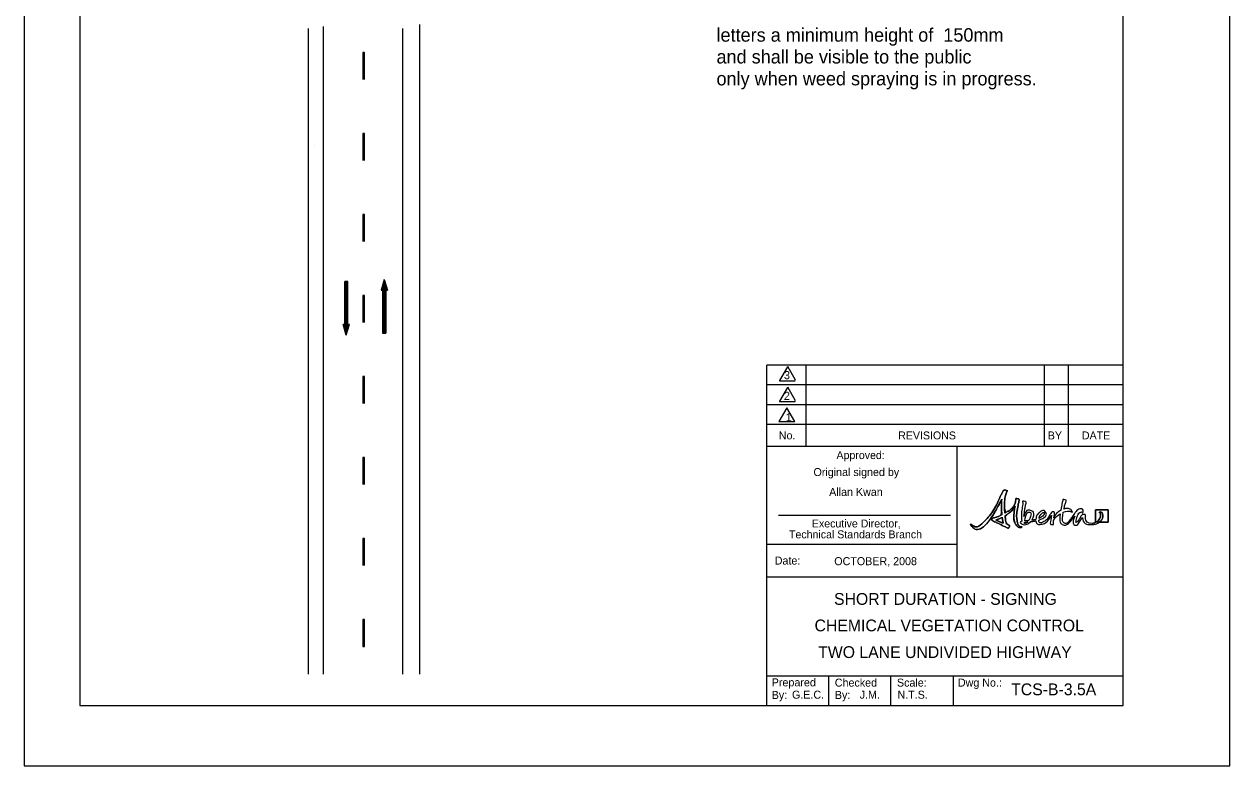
# Model space of a CAD drawing. Extents: x 1578 to 1794, y 169 to 448.
# Drawn here: x 1578.5 to 1794.5, y 169 to 301.9 of the extents above; entities that cross this region are included whole.
import ezdxf

# ---------------------------------------------------------------- set-up
doc = ezdxf.new("R2010")
doc.units = 0
for name, color, linetype in [('Level 10', 7, 'Continuous'), ('Level 2', 7, 'Continuous'), ('Level 53', 7, 'Continuous'), ('Level 60', 7, 'Continuous')]:
    doc.layers.add(name, color=color, linetype=linetype)

msp = doc.modelspace()

# ---------------------------------------------------------------- linework, layer by layer
at = {"layer": 'Level 10'}
for p, q in [((1629.33, 301.16), (1629.33, 185.45)), ((1632.06, 301.53), (1632.06, 185.45)), ((1646.28, 301.16), (1646.28, 185.45)), ((1649.3, 301.9), (1649.3, 185.45)), ((1630.42, 280.2), (1630.42, 280.2)), ((1635.9, 248.11), (1635.9, 255.85)), ((1636.48, 255.85), (1635.9, 255.85)), ((1635.9, 247.15), (1635.9, 255.85)), ((1635.97, 246.9), (1635.97, 255.85)), ((1636.05, 246.66), (1636.05, 255.85)), ((1636.12, 246.42), (1636.12, 255.85)), ((1636.19, 246.18), (1636.19, 255.85)), ((1636.26, 246.42), (1636.26, 255.85)), ((1636.34, 246.66), (1636.34, 255.85)), ((1636.41, 246.9), (1636.41, 255.85)), ((1636.48, 248.11), (1636.48, 255.85)), ((1636.48, 247.15), (1636.48, 255.85)), ((1642.99, 256.21), (1642.41, 254.28)), ((1642.62, 255), (1642.62, 254.28)), ((1642.7, 255.25), (1642.7, 246.54)), ((1642.77, 255.49), (1642.77, 246.54)), ((1642.84, 255.73), (1642.84, 246.54)), ((1642.91, 255.97), (1642.91, 246.54)), ((1642.99, 256.21), (1642.99, 246.54)), ((1642.99, 256.21), (1643.57, 254.28)), ((1643.06, 255.97), (1643.06, 246.54)), ((1643.13, 255.73), (1643.13, 246.54)), ((1643.2, 255.49), (1643.2, 246.54)), ((1643.28, 255.25), (1643.28, 246.54)), ((1643.35, 255), (1643.35, 254.28)), ((1642.41, 254.28), (1642.7, 254.28)), ((1642.48, 254.52), (1642.48, 254.28)), ((1642.55, 254.76), (1642.55, 254.28)), ((1642.7, 254.28), (1642.7, 246.54)), ((1643.28, 254.28), (1643.28, 246.54)), ((1643.28, 254.28), (1643.57, 254.28)), ((1643.42, 254.76), (1643.42, 254.28)), ((1643.49, 254.52), (1643.49, 254.28)), ((1636.19, 246.18), (1635.61, 248.11)), ((1635.9, 248.11), (1635.61, 248.11)), ((1635.68, 247.87), (1635.68, 248.11)), ((1635.75, 247.63), (1635.75, 248.11)), ((1635.83, 247.39), (1635.83, 248.11)), ((1636.19, 246.18), (1636.77, 248.11)), ((1636.77, 248.11), (1636.48, 248.11)), ((1636.55, 247.39), (1636.55, 248.11)), ((1636.63, 247.63), (1636.63, 248.11)), ((1636.7, 247.87), (1636.7, 248.11)), ((1642.7, 246.54), (1643.28, 246.54))]:
    msp.add_line(p, q, dxfattribs=at)
at = {"layer": 'Level 2'}
for p, q in [((1639.15, 296.86), (1639.15, 292.02)), ((1639.44, 296.86), (1639.15, 296.86)), ((1639.44, 292.02), (1639.44, 296.86)), ((1639.15, 282.35), (1639.15, 277.51)), ((1639.44, 282.35), (1639.15, 282.35)), ((1639.44, 277.51), (1639.44, 282.35)), ((1639.15, 267.83), (1639.15, 262.99)), ((1639.44, 267.83), (1639.15, 267.83)), ((1639.44, 262.99), (1639.44, 267.83)), ((1639.15, 253.32), (1639.15, 248.48)), ((1639.44, 253.32), (1639.15, 253.32)), ((1639.44, 248.48), (1639.44, 253.32)), ((1639.15, 238.8), (1639.15, 233.97)), ((1639.44, 238.8), (1639.15, 238.8)), ((1639.44, 233.97), (1639.44, 238.8)), ((1639.15, 224.29), (1639.15, 219.45)), ((1639.44, 224.29), (1639.15, 224.29)), ((1639.44, 219.45), (1639.44, 224.29)), ((1639.15, 209.78), (1639.15, 204.94)), ((1639.44, 209.78), (1639.15, 209.78)), ((1639.44, 204.94), (1639.44, 209.78)), ((1639.15, 195.26), (1639.15, 190.42)), ((1639.44, 195.26), (1639.15, 195.26)), ((1639.44, 190.42), (1639.44, 195.26)), ((1639.15, 190.42), (1639.44, 190.42))]:
    msp.add_line(p, q, dxfattribs=at)
at = {"layer": 'Level 53'}
msp.add_line((1771.03, 212.68), (1770.48, 212.68), dxfattribs=at)
msp.add_lwpolyline([(1771.03, 212.68), (1772.65, 212.68), (1772.65, 214.91), (1770.42, 214.91), (1770.42, 212.68), (1770.48, 212.68)], dxfattribs=at)
for points, degree in [([(1757.05, 211.87), (1756.81, 211.9), (1756.49, 212.23), (1756.4, 212.77), (1756.23, 213.73), (1756.33, 214.69), (1756.61, 216.11), (1756.67, 216.38), (1756.85, 216.84), (1756.27, 216.93), (1756.08, 216.96), (1756.18, 216.87), (1756.12, 216.62), (1755.9, 215.57), (1755.03, 214.8), (1754.16, 214.29), (1754.07, 215.5), (1754.11, 216.85), (1754.34, 217.67), (1754.53, 218.37), (1754.76, 218.24), (1754.48, 218.39), (1754.18, 218.54), (1753.86, 218.34), (1753.6, 217.82), (1753.34, 217.3), (1752.14, 214.49), (1750.23, 212.59), (1749.25, 211.61), (1748.37, 212.11), (1748.19, 212.26), (1748.05, 212.39), (1747.99, 212.2), (1748.17, 212.01), (1748.96, 211.15), (1750.12, 211.64), (1750.54, 212.06), (1751.7, 213.22), (1753.05, 215.73), (1753.6, 216.79), (1753.55, 216.19), (1753.53, 215.19), (1753.64, 214.01), (1753.05, 213.72), (1752.52, 213.55), (1752.27, 213.49), (1752, 213.42), (1751.83, 213.31), (1751.83, 213.18), (1751.82, 213.04), (1752, 212.93), (1752.27, 212.8), (1752.74, 212.58), (1754.11, 211.93), (1754.45, 211.74), (1754.73, 211.57), (1754.88, 211.7), (1754.96, 211.88), (1755.07, 212.12), (1754.77, 212.25), (1754.47, 212.34), (1754.35, 212.74), (1754.26, 213.28), (1754.2, 213.87), (1754.9, 214.3), (1755.59, 214.87), (1755.98, 215.58), (1755.88, 214.98), (1755.63, 212.95), (1756.27, 212.1), (1756.41, 211.91), (1756.72, 211.7), (1757.03, 211.73), (1757.17, 211.74), (1757.24, 211.84), (1757.23, 211.87), (1757.21, 211.9), (1757.13, 211.86), (1757.05, 211.87)], 3), ([(1754.16, 214.29), (1754.07, 215.5), (1754.11, 216.85), (1754.34, 217.67), (1754.53, 218.37), (1754.76, 218.24), (1754.48, 218.39), (1754.18, 218.54), (1753.86, 218.34), (1753.6, 217.82), (1753.34, 217.3), (1752.14, 214.49), (1750.23, 212.59), (1749.25, 211.61), (1748.37, 212.11), (1748.19, 212.26), (1748.05, 212.39), (1747.99, 212.2), (1748.17, 212.01), (1748.96, 211.15), (1750.12, 211.64), (1750.54, 212.06), (1751.7, 213.22), (1753.05, 215.73), (1753.6, 216.79)], 3), ([(1753.6, 216.79), (1753.55, 216.19), (1753.53, 215.19), (1753.64, 214.01)], 2), ([(1757.05, 211.87), (1756.81, 211.9), (1756.49, 212.23), (1756.4, 212.77), (1756.23, 213.73), (1756.33, 214.69), (1756.61, 216.11), (1756.67, 216.38), (1756.85, 216.84), (1756.27, 216.93), (1756.08, 216.96), (1756.18, 216.87), (1756.12, 216.62), (1755.9, 215.57), (1755.03, 214.8), (1754.16, 214.29)], 3), ([(1757.58, 213.71), (1757.63, 214.28), (1757.72, 214.97), (1757.85, 215.61), (1757.9, 215.88), (1758.09, 216.35), (1757.5, 216.44), (1757.32, 216.47), (1757.35, 216.38), (1757.36, 216.13), (1757.38, 215.79), (1757.01, 213.75), (1757.2, 212.86)], 3), ([(1764.74, 215.05), (1764.8, 215.35), (1764.88, 215.65), (1764.96, 215.94), (1765.04, 216.21), (1765.26, 216.68), (1764.68, 216.77), (1764.5, 216.8), (1764.57, 216.71), (1764.51, 216.46), (1764.4, 216), (1764.26, 215.41), (1764.16, 214.81)], 3), ([(1753.64, 214.01), (1753.05, 213.72), (1752.52, 213.55), (1752.27, 213.49), (1752, 213.42), (1751.83, 213.31), (1751.83, 213.18), (1751.82, 213.04), (1752, 212.93), (1752.27, 212.8), (1752.74, 212.58), (1754.11, 211.93), (1754.45, 211.74), (1754.73, 211.57), (1754.88, 211.7), (1754.96, 211.88), (1755.07, 212.12), (1754.77, 212.25), (1754.47, 212.34)], 3), ([(1754.2, 213.87), (1754.9, 214.3), (1755.59, 214.87), (1755.98, 215.58)], 2), ([(1754.47, 212.34), (1754.35, 212.74), (1754.26, 213.28), (1754.2, 213.87)], 2), ([(1755.98, 215.58), (1755.88, 214.98), (1755.63, 212.95), (1756.27, 212.1), (1756.41, 211.91), (1756.72, 211.7), (1757.03, 211.73), (1757.17, 211.74), (1757.24, 211.84), (1757.23, 211.87), (1757.21, 211.9), (1757.13, 211.86), (1757.05, 211.87)], 3), ([(1759.02, 213.05), (1759.44, 213.72), (1759.4, 214.63), (1758.79, 214.78), (1758.09, 214.96), (1757.73, 214.28), (1757.58, 213.71)], 3), ([(1757.73, 212.92), (1757.83, 213.64), (1758.2, 214.63), (1758.66, 214.47), (1758.93, 214.38), (1758.79, 213.54), (1758.45, 212.98)], 3), ([(1760.25, 213.07), (1760.34, 213.1), (1760.43, 213.13), (1760.5, 213.16), (1761.38, 213.55), (1761.69, 214.15), (1761.46, 214.5), (1761.25, 214.85), (1760.64, 214.74), (1760.16, 214.24), (1759.92, 213.99), (1759.74, 213.56), (1759.72, 213.17)], 3), ([(1759.73, 212.95), (1759.78, 212.55), (1760.03, 212.25), (1760.63, 212.31), (1761.47, 212.39), (1762.23, 213.43), (1762.51, 213.93)], 3), ([(1762.92, 213.49), (1762.98, 213.76), (1763.06, 214.07), (1763.07, 214.27), (1763.08, 214.49), (1762.93, 214.54), (1762.87, 214.56), (1762.74, 214.59), (1762.59, 214.53), (1762.44, 214.32), (1762.09, 213.82), (1761.64, 213.03), (1760.96, 212.7), (1760.47, 212.47), (1760.26, 212.7), (1760.25, 213.07)], 3), ([(1760.72, 214.19), (1761.02, 214.47), (1761.16, 214.45), (1761.2, 214.37), (1761.28, 214.21), (1760.94, 213.65), (1760.27, 213.34)], 3), ([(1760.27, 213.34), (1760.33, 213.64), (1760.49, 213.97), (1760.72, 214.19)], 2), ([(1762.51, 213.93), (1762.46, 213.39), (1762.11, 212.22), (1762.7, 212.28), (1762.94, 212.3), (1762.84, 212.34), (1762.85, 212.54), (1762.9, 213.25), (1763.49, 213.85), (1764.07, 214.21)], 3), ([(1764.16, 214.81), (1763.69, 214.54), (1763.24, 214.09), (1762.92, 213.49)], 2), ([(1764.07, 214.21), (1763.97, 213.35), (1764.01, 212.57), (1764.4, 212.33), (1765.12, 211.88), (1766.14, 213.07), (1766.71, 213.79)], 3), ([(1769.79, 212.48), (1768.88, 212.48), (1768.64, 213.19), (1768.6, 213.54), (1768.57, 213.78), (1768.62, 214.12), (1768.21, 214.07), (1767.93, 214.04), (1767.67, 213.49), (1767.32, 213.02), (1767.01, 212.63), (1766.87, 212.66), (1766.94, 213.01), (1767.03, 213.43), (1767.39, 214.44), (1767.8, 214.51), (1767.99, 214.55), (1768.05, 214.21), (1768.14, 214.42), (1768.23, 214.63), (1768.15, 215.08), (1767.72, 215.08), (1767.43, 215.08), (1767.07, 214.77), (1766.78, 214.41), (1766.53, 214.1), (1765.24, 212.2), (1764.7, 212.61), (1764.45, 212.8), (1764.47, 213.58), (1764.63, 214.5)], 3), ([(1764.63, 214.5), (1765.27, 214.74), (1765.8, 214.66), (1766.1, 214.52), (1766.25, 214.45), (1766.27, 214.46), (1766.21, 214.62), (1766.11, 214.86), (1765.6, 215.24), (1764.79, 215.06), (1764.78, 215.06), (1764.76, 215.06), (1764.74, 215.05)], 3), ([(1770.42, 214.91), (1770.42, 214.91), (1770.42, 212.68), (1770.42, 212.68), (1770.42, 212.68), (1770.48, 212.68), (1770.48, 212.68), (1770.97, 212.97), (1771.29, 213.52), (1771.29, 213.98), (1771.29, 214.37), (1771.08, 214.35), (1771.1, 214.41), (1771.17, 214.56), (1771.67, 214.47), (1771.69, 213.92), (1771.72, 213.45), (1771.47, 212.99), (1771.03, 212.68), (1771.03, 212.68), (1772.65, 212.68), (1772.65, 212.68), (1772.65, 212.68), (1772.65, 214.91), (1772.65, 214.91), (1772.65, 214.91), (1770.42, 214.91), (1770.42, 214.91)], 3), ([(1770.48, 212.68), (1770.97, 212.97), (1771.29, 213.52), (1771.29, 213.98), (1771.29, 214.37), (1771.08, 214.35), (1771.1, 214.41), (1771.17, 214.56), (1771.67, 214.47), (1771.69, 213.92), (1771.72, 213.45), (1771.47, 212.99), (1771.03, 212.68)], 3), ([(1752.57, 213.08), (1752.88, 213.19), (1753.28, 213.36), (1753.69, 213.58)], 2), ([(1752.57, 213.08), (1752.88, 213.19), (1753.28, 213.36), (1753.69, 213.58), (1753.75, 213.1), (1753.81, 212.76), (1753.87, 212.51), (1753.57, 212.62), (1753.14, 212.79), (1752.57, 213.08)], 3), ([(1753.87, 212.51), (1753.57, 212.62), (1753.14, 212.79), (1752.57, 213.08)], 2), ([(1753.69, 213.58), (1753.75, 213.1), (1753.81, 212.76), (1753.87, 212.51)], 2), ([(1757.2, 212.86), (1756.95, 212.78), (1756.85, 212.59), (1757.17, 212.39), (1757.4, 212.25), (1757.89, 212.21), (1758.38, 212.45), (1758.56, 212.54), (1758.71, 212.66), (1758.84, 212.8)], 3), ([(1757.66, 212.49), (1757.69, 212.51), (1757.71, 212.55), (1757.71, 212.6), (1757.71, 212.63), (1757.71, 212.67), (1757.71, 212.7)], 3), ([(1757.86, 212.49), (1757.78, 212.48), (1757.71, 212.48), (1757.66, 212.49)], 2), ([(1757.71, 212.7), (1757.84, 212.7), (1758.04, 212.72), (1758.27, 212.74)], 2), ([(1758.45, 212.98), (1758.22, 212.96), (1757.98, 212.94), (1757.73, 212.92)], 2), ([(1758.27, 212.74), (1758.15, 212.61), (1758.01, 212.51), (1757.86, 212.49)], 2), ([(1758.84, 212.8), (1759.14, 212.84), (1759.45, 212.89), (1759.73, 212.95)], 2), ([(1759.72, 213.17), (1759.52, 213.12), (1759.28, 213.08), (1759.02, 213.05)], 2), ([(1766.71, 213.79), (1766.42, 213.15), (1766.26, 212.32), (1766.69, 212.19), (1767.19, 212.05), (1767.59, 212.88), (1768.06, 213.53)], 3), ([(1768.06, 213.53), (1768.11, 213.07), (1768.42, 212.27), (1769.65, 212.27), (1770.21, 212.27), (1770.68, 212.43), (1771.03, 212.68)], 3), ([(1770.48, 212.68), (1770.28, 212.56), (1770.04, 212.48), (1769.79, 212.48)], 2)]:
    msp.add_open_spline(points, degree=degree, dxfattribs=at)
at = {"layer": 'Level 60'}
for p, q in [((1711.5, 234.37), (1711.5, 240.84)), ((1775.38, 240.84), (1711.5, 240.84)), ((1718.59, 234.37), (1718.59, 240.84)), ((1761.18, 240.84), (1761.18, 226.29)), ((1765.49, 240.84), (1765.49, 226.29)), ((1775.38, 237.29), (1711.5, 237.29)), ((1711.5, 226.29), (1711.5, 234.37)), ((1775.38, 233.75), (1711.5, 233.75)), ((1718.59, 226.29), (1718.59, 234.37)), ((1775.38, 230.2), (1711.5, 230.2)), ((1745.72, 228.68), (1745.72, 228.68)), ((1711.5, 179.83), (1711.5, 226.29)), ((1711.5, 226.29), (1775.38, 226.29)), ((1745.55, 226.29), (1745.55, 202.88)), ((1745.57, 226.29), (1745.57, 226.29)), ((1713.61, 213.98), (1744.41, 213.98)), ((1711.5, 208.74), (1745.55, 208.74)), ((1711.5, 202.88), (1775.35, 202.88)), ((1711.5, 185.15), (1775.35, 185.15)), ((1722.63, 179.83), (1722.63, 185.15)), ((1733.76, 179.83), (1733.76, 185.15)), ((1744.89, 185.15), (1744.89, 179.83)), ((1588.47, 179.83), (1588.47, 179.83)), ((1726.97, 179.83), (1726.97, 179.83)), ((1775.35, 179.83), (1775.35, 179.83)), ((1775.35, 179.83), (1775.35, 179.83)), ((1578.47, 169.02), (1578.47, 169.02))]:
    msp.add_line(p, q, dxfattribs=at)
for points in [[(1794.47, 448.02), (1578.47, 448.02), (1578.47, 169.02), (1794.47, 169.02)], [(1775.35, 437.21), (1588.47, 437.21), (1588.47, 179.83), (1775.35, 179.83)], [(1715.12, 233.18), (1713.7, 230.71), (1716.54, 230.71)]]:
    msp.add_lwpolyline(points, close=True, dxfattribs=at)
for points in [[(1715.2, 240.51), (1713.81, 238.09)], [(1716.68, 238.16), (1715.29, 240.59)], [(1713.81, 238.09), (1713.78, 238.04), (1716.62, 238.04), (1716.6, 238.09)], [(1715.2, 236.8), (1713.81, 234.37)], [(1716.68, 234.45), (1715.29, 236.87)], [(1713.81, 234.37), (1713.78, 234.33), (1716.62, 234.33), (1716.6, 234.37)]]:
    msp.add_lwpolyline(points, dxfattribs=at)

# ---------------------------------------------------------------- texts
at = {"layer": 'Level 10'}
for s, p in [('  letters a minimum height of  150mm', (1700.71, 298.8)), ('  and shall be visible to the public', (1700.71, 294.89)), ('  only when weed spraying is in progress.', (1700.71, 290.97))]:
    msp.add_text(s, height=2.419, dxfattribs=at).set_placement(p)
at = {"layer": 'Level 60'}
for s, height, p in [('3', 1.45, (1714.59, 238.31)), ('2', 1.45, (1714.58, 234.6)), ('1', 1.45, (1714.9, 230.77)), ('REVISIONS', 1.419, (1735.06, 227.53)), ('No.', 1.419, (1713.68, 227.53)), ('BY', 1.419, (1761.86, 227.53)), ('DATE', 1.419, (1767.97, 227.53)), ('Date:', 1.433, (1712.94, 205.1)), ('SHORT DURATION - SIGNING', 2.115, (1723.56, 197.88)), ('CHEMICAL VEGETATION CONTROL', 2.115, (1720.07, 193.13)), ('Prepared', 1.44, (1712.39, 183.27)), ('Checked', 1.433, (1723.7, 183.23)), ('Scale:', 1.433, (1734.83, 183.23)), ('Dwg No.:', 1.433, (1745.75, 183.23)), ('By:', 1.44, (1712.39, 181.01)), ('G.E.C.', 1.433, (1716.03, 181.07)), ('By:', 1.44, (1723.7, 181.01)), ('J.M.', 1.433, (1728.16, 181.07)), ('    N.T.S.   ', 1.4329, (1732.8, 181.06))]:
    msp.add_text(s, height=height, rotation=360, dxfattribs=at).set_placement(p)
for s, height, p in [('Approved:', 1.419, (1724, 224)), ('Original signed by', 1.434, (1719.88, 220.96)), ('Allan Kwan', 1.434, (1722.69, 217.4)), ('Executive Director,', 1.4187, (1719.59, 211.75)), ('Technical Standards Branch', 1.4187, (1715.49, 209.8)), ('OCTOBER, 2008', 1.434, (1723.6, 204.99)), ('TWO LANE UNDIVIDED HIGHWAY', 2.1152, (1720.72, 188.35)), ('TCS-B-3.5A', 2.115, (1755.29, 181.68))]:
    msp.add_text(s, height=height, dxfattribs=at).set_placement(p)

doc.saveas('drawing.dxf')
